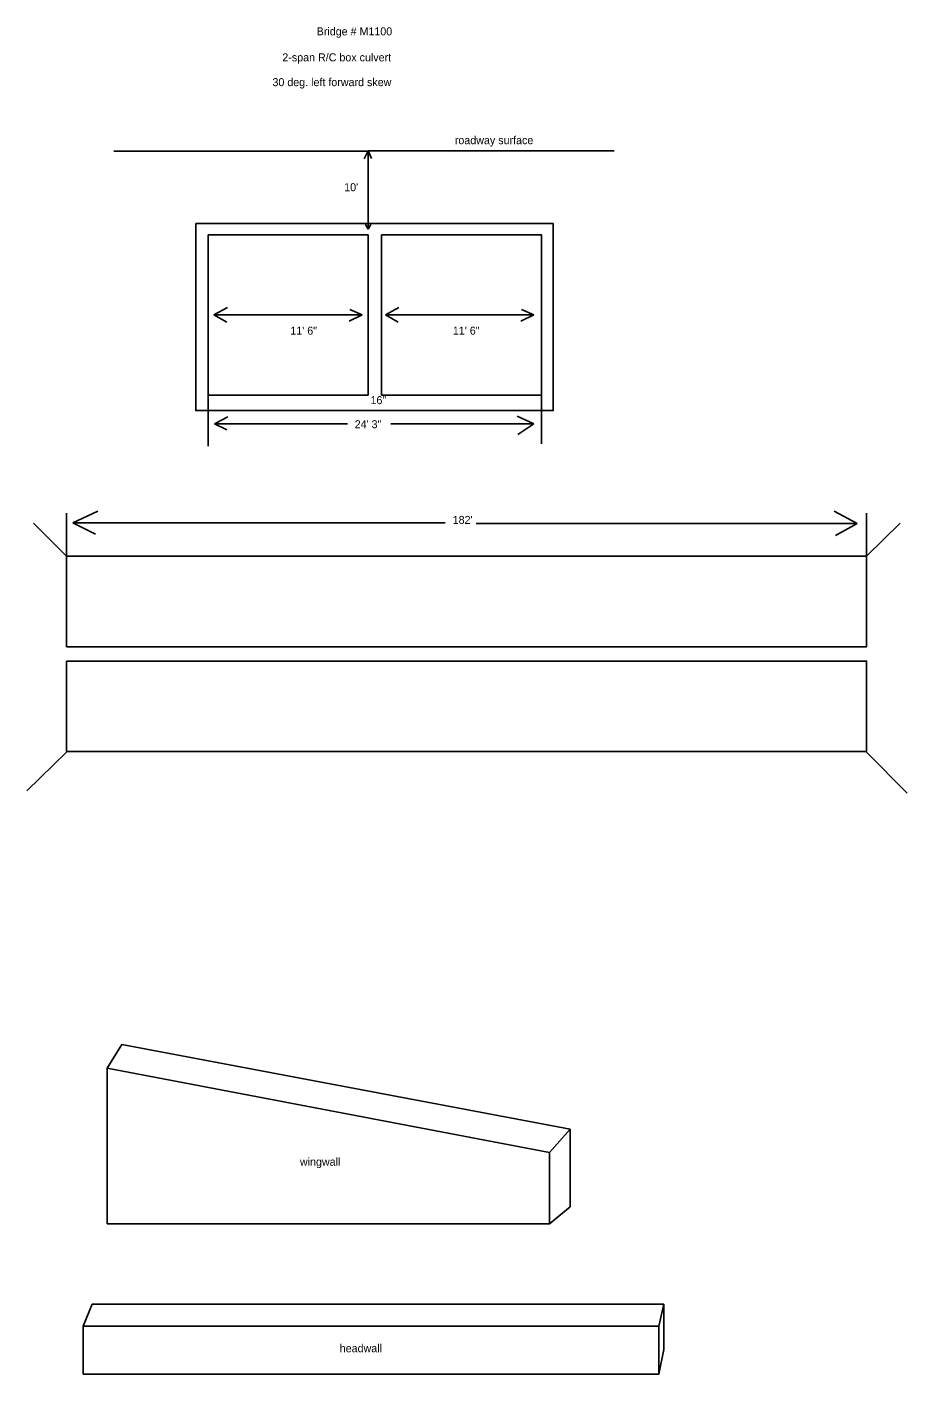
# Model space of a CAD drawing. Extents: x -629.7 to -574.7, y -353.6 to -269.4.
import ezdxf

# ---------------------------------------------------------------- set-up
doc = ezdxf.new("R2010")
doc.units = 0
doc.layers.add('Default', color=7, linetype='Continuous')

msp = doc.modelspace()

# ---------------------------------------------------------------- linework, layer by layer
at = {"layer": 'Default'}
for p, q in [((-608.395, -277.153), (-624.305, -277.153)), ((-608.404, -277.151), (-608.656, -277.636)), ((-608.404, -277.151), (-608.404, -281.469)), ((-608.404, -277.151), (-593.023, -277.151)), ((-608.404, -277.151), (-608.188, -277.612)), ((-608.404, -282.033), (-608.568, -281.752)), ((-608.404, -281.469), (-608.404, -282.033)), ((-608.404, -282.033), (-608.23, -281.752)), ((-618.035, -287.395), (-617.196, -286.924)), ((-608.765, -287.395), (-609.543, -287.047)), ((-607.312, -287.395), (-606.473, -286.924)), ((-598.042, -287.395), (-598.82, -287.047)), ((-618.035, -287.395), (-608.765, -287.395)), ((-618.035, -287.395), (-617.237, -287.845)), ((-608.765, -287.395), (-609.584, -287.784)), ((-607.312, -287.395), (-598.042, -287.395)), ((-607.312, -287.395), (-606.514, -287.845)), ((-598.042, -287.395), (-598.861, -287.784)), ((-618.404, -292.401), (-618.404, -295.589)), ((-597.564, -292.401), (-597.564, -295.456)), ((-618.014, -294.203), (-617.165, -293.767)), ((-598.048, -294.206), (-599.077, -293.728)), ((-618.014, -294.203), (-617.227, -294.576)), ((-618.014, -294.203), (-609.696, -294.203)), ((-606.977, -294.206), (-598.048, -294.206)), ((-598.048, -294.206), (-599.04, -294.868)), ((-626.864, -300.384), (-625.289, -299.667)), ((-577.839, -300.42), (-579.271, -299.667)), ((-627.248, -302.481), (-629.318, -300.418)), ((-627.248, -302.481), (-627.248, -299.775)), ((-603.587, -300.384), (-626.864, -300.384)), ((-626.864, -300.384), (-625.432, -301.1)), ((-601.653, -300.42), (-577.839, -300.42)), ((-577.839, -300.42), (-579.199, -301.172)), ((-577.248, -302.481), (-577.248, -299.775)), ((-577.248, -302.481), (-575.141, -300.418)), ((-627.248, -314.724), (-629.727, -317.145)), ((-577.248, -314.724), (-574.717, -317.272)), ((-624.713, -334.467), (-623.805, -332.984)), ((-623.805, -332.984), (-595.776, -338.273)), ((-624.713, -334.467), (-624.713, -344.186)), ((-624.713, -334.467), (-597.056, -339.743)), ((-597.056, -339.743), (-595.776, -338.273)), ((-595.776, -338.273), (-595.776, -343.139)), ((-597.056, -344.186), (-597.056, -339.743)), ((-597.056, -344.186), (-595.776, -343.139)), ((-624.713, -344.186), (-597.056, -344.186)), ((-626.212, -350.582), (-625.644, -349.207)), ((-625.644, -349.207), (-589.913, -349.207)), ((-590.23, -350.582), (-589.913, -349.207)), ((-589.913, -349.207), (-589.913, -349.207)), ((-589.913, -349.207), (-589.913, -352.038)), ((-626.212, -350.582), (-590.23, -350.582)), ((-626.212, -350.582), (-626.212, -353.582)), ((-590.23, -350.582), (-590.23, -353.582)), ((-589.913, -352.038), (-590.23, -353.582)), ((-626.212, -353.582), (-590.23, -353.582))]:
    msp.add_line(p, q, dxfattribs=at)
for points in [[(-619.179, -281.693), (-596.834, -281.693), (-596.834, -293.369), (-619.179, -293.369)], [(-618.404, -282.401), (-608.404, -282.401), (-608.404, -292.401), (-618.404, -292.401)], [(-607.564, -282.401), (-597.564, -282.401), (-597.564, -292.401), (-607.564, -292.401)], [(-627.248, -302.481), (-577.248, -302.481), (-577.248, -308.127), (-627.248, -308.127)], [(-627.248, -309.026), (-577.248, -309.026), (-577.248, -314.672), (-627.248, -314.672)]]:
    msp.add_lwpolyline(points, close=True, dxfattribs=at)

# ---------------------------------------------------------------- texts
for s, p in [('Bridge # M1100', (-611.617, -269.926)), ('2-span R/C box culvert', (-613.764, -271.55)), ('30 deg. left forward skew', (-614.381, -273.1)), ('roadway surface', (-602.983, -276.727)), ("10'", (-609.898, -279.665)), ('11\' 6"', (-613.263, -288.63)), ('11\' 6"', (-603.106, -288.63)), ('16"', (-608.252, -292.972)), ('24\' 3"', (-609.242, -294.477)), ("182'", (-603.116, -300.455)), ('wingwall', (-612.663, -340.563)), ('headwall', (-610.175, -352.218))]:
    msp.add_text(s, height=0.5, dxfattribs=at).set_placement(p)

doc.saveas('drawing.dxf')
